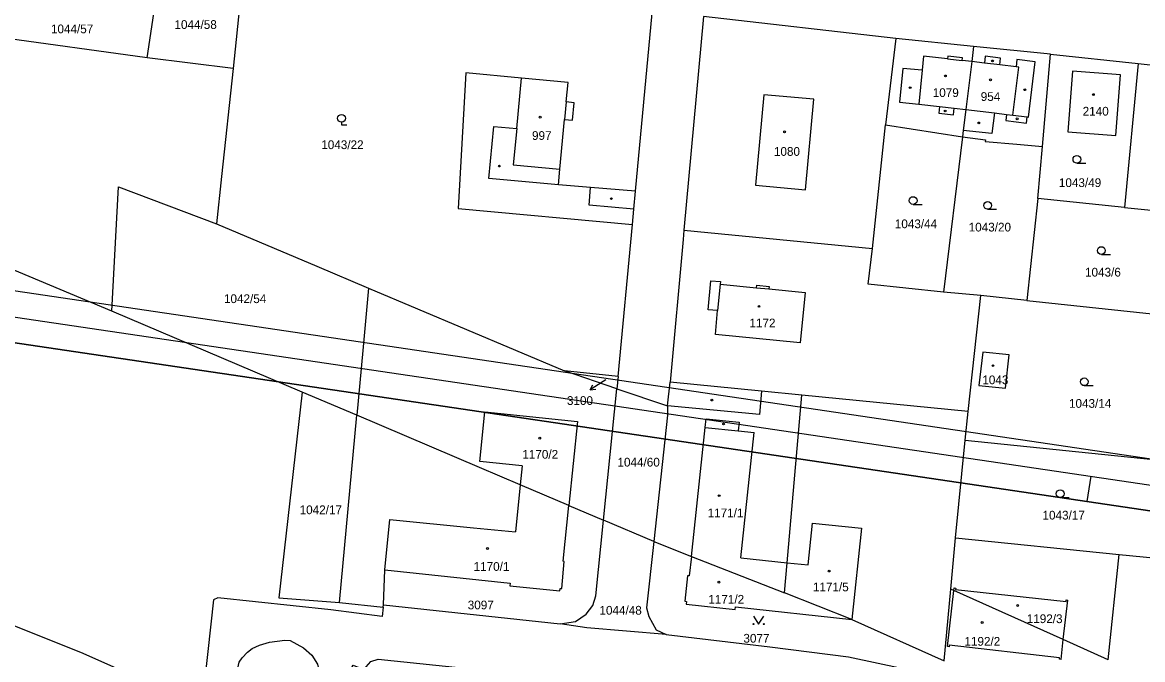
# Model space of a CAD drawing. Extents: x -779330 to -774454, y -1144748 to -1142831.
# Drawn here: x -775422.9 to -775205.5, y -1144345.1 to -1144221.4 of the extents above; entities that cross this region are included whole.
import ezdxf

# ---------------------------------------------------------------- set-up
doc = ezdxf.new("R2010")
doc.units = 0
for name, color, linetype in [('Hranice parcel', 7, 'Continuous'), ('Parcelní čísla', 7, 'Continuous'), ('Pop  PČ popisy', 7, 'Continuous'), ('Vnitřní kresba', 7, 'Continuous'), ('Vrstva 1', 7, 'Continuous'), ('Značky budov', 7, 'Continuous'), ('Značky kultur', 7, 'Continuous')]:
    doc.layers.add(name, color=color, linetype=linetype)

msp = doc.modelspace()

# ---------------------------------------------------------------- linework, layer by layer
at = {"layer": 'Hranice parcel'}
for p, q in [((-775380.44, -1144215.31), (-775382.05, -1144230.36)), ((-775398.7, -1144228.28), (-775397.42, -1144219.68)), ((-775303.9, -1144254.18), (-775300.69, -1144219.59)), ((-775290.72, -1144220.22), (-775294.52, -1144261.7)), ((-775253.4, -1144224.49), (-775290.72, -1144220.22)), ((-775398.7, -1144228.28), (-775442.24, -1144222.22)), ((-775253.4, -1144224.49), (-775255.39, -1144241.28)), ((-775238.28, -1144226.05), (-775253.4, -1144224.49)), ((-775223.36, -1144227.59), (-775238.28, -1144226.05)), ((-775382.05, -1144230.36), (-775398.7, -1144228.28)), ((-775224.92, -1144245.46), (-775223.36, -1144227.59)), ((-775223.36, -1144227.59), (-775206.34, -1144229.39)), ((-775206.34, -1144229.39), (-775208.99, -1144257.32)), ((-775206.34, -1144229.39), (-775195.14, -1144230.58)), ((-775257.93, -1144265.27), (-775255.39, -1144241.28)), ((-775255.39, -1144241.28), (-775240.44, -1144243.62)), ((-775240.44, -1144243.62), (-775244.14, -1144273.78)), ((-775225.81, -1144255.6), (-775224.92, -1144245.46)), ((-775405.59, -1144277.47), (-775404.31, -1144253.32)), ((-775404.31, -1144253.32), (-775385.27, -1144260.49)), ((-775225.81, -1144255.6), (-775227.98, -1144275.38)), ((-775208.99, -1144257.32), (-775225.81, -1144255.6)), ((-775208.99, -1144257.32), (-775197.16, -1144258.53)), ((-775307.31, -1144290.13), (-775304.52, -1144260.66)), ((-775294.52, -1144261.7), (-775257.93, -1144265.27)), ((-775355.73, -1144272.99), (-775317.7, -1144289.07)), ((-775236.87, -1144274.43), (-775244.14, -1144273.78)), ((-775239.33, -1144296.93), (-775236.87, -1144274.43)), ((-775227.98, -1144275.38), (-775236.87, -1144274.43)), ((-775227.98, -1144275.38), (-775199.27, -1144278.47)), ((-775368.6, -1144293.2), (-775405.59, -1144277.47)), ((-775307.31, -1144290.13), (-775317.7, -1144289.07)), ((-775307.55, -1144292.51), (-775317.7, -1144289.07)), ((-775307.31, -1144290.13), (-775307.55, -1144292.51)), ((-775297.71, -1144295.85), (-775297.22, -1144291.22)), ((-775279.43, -1144292.98), (-775297.22, -1144291.22)), ((-775358.04, -1144297.68), (-775368.6, -1144293.2)), ((-775310.14, -1144318.05), (-775307.55, -1144292.51)), ((-775307.55, -1144292.51), (-775297.71, -1144295.85)), ((-775271.6, -1144293.75), (-775279.43, -1144292.98)), ((-775239.33, -1144296.93), (-775271.6, -1144293.75)), ((-775361.4, -1144334), (-775358.04, -1144297.68)), ((-775239.94, -1144302.5), (-775239.33, -1144296.93)), ((-775241.77, -1144321.45), (-775239.94, -1144302.5)), ((-775239.94, -1144302.5), (-775200.81, -1144306.5)), ((-775317.99, -1144326.02), (-775316.86, -1144315.19)), ((-775316.86, -1144315.19), (-775310.14, -1144318.05)), ((-775300.37, -1144322.2), (-775310.14, -1144318.05)), ((-775300.37, -1144322.2), (-775293.07, -1144325.07)), ((-775242.71, -1144331.45), (-775241.77, -1144321.45)), ((-775241.77, -1144321.45), (-775210.05, -1144324.7)), ((-775212.14, -1144345.14), (-775210.05, -1144324.7)), ((-775210.05, -1144324.7), (-775202.71, -1144325.45)), ((-775293.07, -1144325.07), (-775293.48, -1144328.88)), ((-775293.07, -1144325.07), (-775275, -1144332.17)), ((-775244.01, -1144345.37), (-775242.71, -1144331.45)), ((-775261.93, -1144337.3), (-775275, -1144332.17)), ((-775361.4, -1144334), (-775352.89, -1144334.93)), ((-775352.89, -1144334.93), (-775352.84, -1144334.48)), ((-775352.84, -1144334.48), (-775318.54, -1144338.18)), ((-775284.53, -1144334.88), (-775261.93, -1144337.3)), ((-775261.93, -1144337.3), (-775244.01, -1144345.37))]:
    msp.add_line(p, q, dxfattribs=at)
for points in [[(-775238.28, -1144226.05), (-775238.64, -1144228.98), (-775239.78, -1144238.29), (-775240.29, -1144242.38), (-775240.44, -1144243.62)], [(-775382.05, -1144230.36), (-775384.29, -1144251.32), (-775385.27, -1144260.49)], [(-775303.9, -1144254.18), (-775312.63, -1144253.44), (-775318.9, -1144252.95), (-775318.61, -1144249.89), (-775317.7, -1144240.23), (-775316.15, -1144240.38), (-775315.82, -1144236.99), (-775317.37, -1144236.84), (-775317.02, -1144233.06), (-775326.05, -1144232.25), (-775336.89, -1144231.21), (-775338.37, -1144257.53), (-775304.52, -1144260.66)], [(-775219.08, -1144230.87), (-775219.98, -1144242.63), (-775210.66, -1144243.34), (-775209.76, -1144231.58), (-775219.08, -1144230.87)], [(-775405.59, -1144277.47), (-775483.88, -1144244.62), (-775508.4, -1144232.87)], [(-775240.44, -1144243.62), (-775235.97, -1144244.17), (-775236.02, -1144244.52), (-775229.92, -1144245.04), (-775224.92, -1144245.46)], [(-775607.93, -1144251.93), (-775592.73, -1144265.24), (-775577.44, -1144273.94), (-775563.67, -1144281.5), (-775543.76, -1144290.79), (-775411.19, -1144343.87), (-775388.13, -1144354.18)], [(-775304.52, -1144260.66), (-775304.24, -1144257.67), (-775303.9, -1144254.18)], [(-775385.27, -1144260.49), (-775365.81, -1144268.72), (-775355.73, -1144272.99)], [(-775294.52, -1144261.7), (-775294.69, -1144263.54), (-775297.22, -1144291.22)], [(-775244.14, -1144273.78), (-775258.75, -1144272.2), (-775257.93, -1144265.27)], [(-775355.73, -1144272.99), (-775356.87, -1144285.07), (-775358.04, -1144297.68)], [(-775231.36, -1144285.93), (-775236.51, -1144285.43), (-775237.28, -1144291.9), (-775232.07, -1144292.44), (-775231.36, -1144285.93)], [(-775368.6, -1144293.2), (-775373.15, -1144333.15), (-775361.4, -1144334)], [(-775275, -1144332.17), (-775274.48, -1144326.3), (-775271.6, -1144293.75)], [(-775297.71, -1144295.85), (-775297.7, -1144297.68), (-775300.37, -1144322.2)], [(-775316.86, -1144315.19), (-775326.32, -1144311.17), (-775334.23, -1144307.8), (-775358.04, -1144297.68)], [(-775318.54, -1144338.18), (-775315.57, -1144337.72), (-775313.52, -1144336.29), (-775312.2, -1144334.62), (-775311.63, -1144332.74), (-775310.14, -1144318.05)], [(-775300.37, -1144322.2), (-775301.77, -1144335.08), (-775301.32, -1144336.73), (-775299.9, -1144339.36), (-775297.97, -1144340.23)], [(-775352.84, -1144334.48), (-775352.58, -1144327.67), (-775328.26, -1144330.26), (-775328.31, -1144330.76), (-775318.6, -1144331.78), (-775318.54, -1144331.28), (-775318.25, -1144331.31), (-775317.74, -1144326.04), (-775317.99, -1144326.02)], [(-775293.48, -1144328.88), (-775293.83, -1144328.85), (-775294.35, -1144333.79), (-775294, -1144333.83), (-775294.06, -1144334.38), (-775284.59, -1144335.4), (-775284.53, -1144334.88)], [(-775212.14, -1144345.14), (-775220.88, -1144341.23), (-775242.11, -1144331.72), (-775242.71, -1144331.45)], [(-775352.89, -1144334.93), (-775353.07, -1144336.72), (-775363.07, -1144335.42), (-775385.03, -1144333.14), (-775385.87, -1144333.51), (-775388.13, -1144354.18)], [(-775297.97, -1144340.23), (-775313.36, -1144338.94), (-775318.54, -1144338.18)], [(-775382.3, -1144356.79), (-775381.59, -1144350.71), (-775381.29, -1144347.59), (-775380.83, -1144345.6), (-775380.26, -1144344.77), (-775379.26, -1144343.66), (-775378.34, -1144342.94), (-775376.9, -1144342.31), (-775374.94, -1144341.74), (-775371.99, -1144341.37), (-775370.97, -1144341.43), (-775368.36, -1144342.85), (-775366.76, -1144344.24), (-775365.64, -1144345.98), (-775364.98, -1144348.92), (-775365.24, -1144350.84), (-775365.71, -1144357.91), (-775366.41, -1144363.89)], [(-775297.97, -1144340.23), (-775277.83, -1144342.65), (-775262.59, -1144344.6), (-775251.95, -1144346.82), (-775244.32, -1144348.69)], [(-775362.68, -1144365.56), (-775362.08, -1144358.58), (-775360.56, -1144350.54), (-775360.06, -1144348.55), (-775358.72, -1144346.19), (-775356.63, -1144347.01), (-775355.33, -1144345.46), (-775353.88, -1144345), (-775329.64, -1144347.57), (-775327.49, -1144348.55), (-775323.08, -1144349.72), (-775321.94, -1144352.56), (-775321.52, -1144355.68), (-775321.75, -1144362.33), (-775323.77, -1144382.71)]]:
    msp.add_lwpolyline(points, dxfattribs=at)
at = {"layer": 'Pop  PČ popisy'}
for p, q in [((-775310.23, -1144291.1), (-775312.75, -1144292.73)), ((-775312.75, -1144292.73), (-775312.18, -1144291.77)), ((-775309.71, -1144290.77), (-775310.23, -1144291.1)), ((-775312.75, -1144292.73), (-775311.63, -1144292.61))]:
    msp.add_line(p, q, dxfattribs=at)
at = {"layer": 'Vnitřní kresba'}
for p, q in [((-775248.04, -1144227.94), (-775248.3, -1144230.68)), ((-775243.36, -1144228.46), (-775248.04, -1144227.94)), ((-775243.31, -1144227.96), (-775243.36, -1144228.46)), ((-775243.36, -1144228.46), (-775240.53, -1144228.77)), ((-775240.47, -1144228.27), (-775243.31, -1144227.96)), ((-775240.53, -1144228.77), (-775240.47, -1144228.27)), ((-775238.64, -1144228.98), (-775240.53, -1144228.77)), ((-775236.19, -1144229.29), (-775238.64, -1144228.98)), ((-775236.04, -1144227.97), (-775236.19, -1144229.29)), ((-775233.22, -1144229.64), (-775236.19, -1144229.29)), ((-775233.07, -1144228.31), (-775236.04, -1144227.97)), ((-775233.22, -1144229.64), (-775233.07, -1144228.31)), ((-775229.87, -1144228.62), (-775230.04, -1144230.03)), ((-775226.34, -1144229.05), (-775229.87, -1144228.62)), ((-775227.63, -1144239.78), (-775226.34, -1144229.05)), ((-775252.03, -1144230.33), (-775252.65, -1144236.88)), ((-775248.3, -1144230.68), (-775252.03, -1144230.33)), ((-775248.3, -1144230.68), (-775248.92, -1144237.29)), ((-775230.04, -1144230.03), (-775233.22, -1144229.64)), ((-775230.65, -1144239.41), (-775229.51, -1144230.1)), ((-775229.51, -1144230.1), (-775230.04, -1144230.03)), ((-775326.99, -1144242.01), (-775326.05, -1144232.25)), ((-775279.04, -1144235.44), (-775280.61, -1144252.99)), ((-775269.33, -1144236.28), (-775279.04, -1144235.44)), ((-775317.37, -1144236.84), (-775317.7, -1144240.23)), ((-775270.94, -1144253.9), (-775269.33, -1144236.28)), ((-775252.65, -1144236.88), (-775248.92, -1144237.29)), ((-775248.92, -1144237.29), (-775244.89, -1144237.73)), ((-775244.89, -1144237.73), (-775245.03, -1144239.02)), ((-775244.89, -1144237.73), (-775242.06, -1144238.04)), ((-775245.03, -1144239.02), (-775242.2, -1144239.33)), ((-775242.2, -1144239.33), (-775242.06, -1144238.04)), ((-775242.06, -1144238.04), (-775239.78, -1144238.29)), ((-775239.78, -1144238.29), (-775234.26, -1144238.97)), ((-775234.26, -1144238.97), (-775234.75, -1144242.97)), ((-775234.26, -1144238.97), (-775231.89, -1144239.26)), ((-775231.89, -1144239.26), (-775232.03, -1144240.45)), ((-775231.89, -1144239.26), (-775230.65, -1144239.41)), ((-775230.65, -1144239.41), (-775227.88, -1144239.75)), ((-775228.02, -1144240.94), (-775227.88, -1144239.75)), ((-775227.88, -1144239.75), (-775227.63, -1144239.78)), ((-775332.42, -1144251.67), (-775331.42, -1144241.59)), ((-775331.42, -1144241.59), (-775326.99, -1144242.01)), ((-775326.99, -1144242.01), (-775327.66, -1144249.03)), ((-775232.03, -1144240.45), (-775228.02, -1144240.94)), ((-775234.75, -1144242.97), (-775240.29, -1144242.38)), ((-775327.66, -1144249.03), (-775318.61, -1144249.89)), ((-775318.9, -1144252.95), (-775332.42, -1144251.67)), ((-775280.61, -1144252.99), (-775270.94, -1144253.9)), ((-775312.92, -1144256.88), (-775312.63, -1144253.44)), ((-775304.24, -1144257.67), (-775312.92, -1144256.88)), ((-775289.81, -1144277.19), (-775289.28, -1144271.56)), ((-775289.28, -1144271.56), (-775287.44, -1144271.73)), ((-775287.49, -1144272.23), (-775287.98, -1144277.36)), ((-775287.44, -1144271.73), (-775287.49, -1144272.23)), ((-775287.49, -1144272.23), (-775280.44, -1144272.91)), ((-775280.44, -1144272.91), (-775280.39, -1144272.41)), ((-775280.39, -1144272.41), (-775277.97, -1144272.65)), ((-775277.97, -1144272.65), (-775278.02, -1144273.15)), ((-775280.44, -1144272.91), (-775278.02, -1144273.15)), ((-775278.02, -1144273.15), (-775271, -1144273.83)), ((-775271, -1144273.83), (-775271.96, -1144283.61)), ((-775287.98, -1144277.36), (-775289.81, -1144277.19)), ((-775288.42, -1144282), (-775287.98, -1144277.36)), ((-775271.96, -1144283.61), (-775288.42, -1144282)), ((-775279.43, -1144292.98), (-775279.88, -1144297.55)), ((-775279.88, -1144297.55), (-775297.71, -1144295.85)), ((-775334.12, -1144306.68), (-775333.15, -1144296.98)), ((-775333.15, -1144296.98), (-775315.15, -1144298.9)), ((-775290.4, -1144300.03), (-775290.22, -1144298.34)), ((-775290.22, -1144298.34), (-775283.8, -1144299.03)), ((-775315.15, -1144298.9), (-775316.86, -1144315.19)), ((-775293.07, -1144325.07), (-775290.4, -1144300.03)), ((-775290.4, -1144300.03), (-775283.98, -1144300.72)), ((-775283.8, -1144299.03), (-775283.98, -1144300.72)), ((-775283.98, -1144300.72), (-775280.9, -1144301.05)), ((-775283.48, -1144325.34), (-775280.9, -1144301.05)), ((-775325.95, -1144307.49), (-775334.12, -1144306.68)), ((-775325.95, -1144307.49), (-775326.32, -1144311.17)), ((-775326.32, -1144311.17), (-775327.23, -1144320.33)), ((-775352.58, -1144327.67), (-775351.61, -1144317.92)), ((-775351.61, -1144317.92), (-775335.39, -1144319.52)), ((-775335.39, -1144319.52), (-775327.23, -1144320.33)), ((-775270.43, -1144326.73), (-775269.55, -1144318.6)), ((-775269.55, -1144318.6), (-775260.03, -1144319.62)), ((-775260.03, -1144319.62), (-775261.93, -1144337.3)), ((-775283.48, -1144325.34), (-775274.48, -1144326.3)), ((-775274.48, -1144326.3), (-775270.43, -1144326.73)), ((-775242.11, -1144331.72), (-775242.05, -1144331.19)), ((-775242.05, -1144331.19), (-775241.75, -1144331.22)), ((-775241.75, -1144331.22), (-775241.79, -1144331.52)), ((-775243.36, -1144342.6), (-775242.11, -1144331.72)), ((-775241.79, -1144331.52), (-775220.32, -1144333.83)), ((-775220.88, -1144341.23), (-775219.99, -1144333.56)), ((-775220.32, -1144333.83), (-775220.29, -1144333.53)), ((-775220.29, -1144333.53), (-775219.99, -1144333.56)), ((-775243.02, -1144342.34), (-775243.06, -1144342.64)), ((-775221.59, -1144344.75), (-775243.02, -1144342.34)), ((-775221.32, -1144345.09), (-775220.88, -1144341.23)), ((-775243.06, -1144342.64), (-775243.36, -1144342.6)), ((-775221.62, -1144345.05), (-775221.59, -1144344.75)), ((-775221.32, -1144345.09), (-775221.62, -1144345.05))]:
    msp.add_line(p, q, dxfattribs=at)
at = {"layer": 'Vrstva 1'}
msp.add_line((-775216.22, -1144314.43), (-775215.49, -1144309.48), dxfattribs=at)
for points in [[(-774799.29, -1144366.04), (-776045.7, -1144181.56), (-776089.18, -1144475.34), (-774842.77, -1144659.83)], [(-774846.98, -1144654.15), (-776083.5, -1144471.13), (-776041.48, -1144187.23), (-774804.97, -1144370.25)], [(-774810.64, -1144374.46), (-775834.48, -1144222.92), (-775875.04, -1144496.94), (-774851.19, -1144648.48)], [(-774851.19, -1144648.48), (-775875.04, -1144496.94), (-775834.48, -1144222.92), (-774810.64, -1144374.46)]]:
    msp.add_lwpolyline(points, close=True, dxfattribs=at)
at = {"layer": 'Značky budov'}
for centre in [(-775234.63, -1144228.87), (-775243.76, -1144231.79), (-775235.01, -1144232.55), (-775250.59, -1144234.06), (-775228.35, -1144234.46), (-775215.03, -1144235.41), (-775322.44, -1144239.8), (-775243.8, -1144238.59), (-775229.84, -1144240.12), (-775237.29, -1144240.91), (-775274.97, -1144242.64), (-775330.35, -1144249.29), (-775308.61, -1144255.61), (-775279.95, -1144276.53), (-775234.52, -1144288.04), (-775289.1, -1144294.72), (-775286.82, -1144299.37), (-775322.51, -1144302.13), (-775287.68, -1144313.28), (-775332.64, -1144323.54), (-775266.33, -1144327.92), (-775287.73, -1144330.09), (-775229.73, -1144334.61), (-775236.63, -1144337.92)]:
    msp.add_circle(centre, 0.175, dxfattribs=at)
at = {"layer": 'Značky kultur'}
for p, q in [((-775360.99, -1144240.76), (-775360.99, -1144241.26)), ((-775360.99, -1144241.26), (-775359.99, -1144241.26)), ((-775218.24, -1144248.73), (-775216.49, -1144248.73)), ((-775250.02, -1144256.73), (-775248.27, -1144256.73)), ((-775235.56, -1144257.68), (-775233.81, -1144257.68)), ((-775213.48, -1144266.44), (-775211.73, -1144266.44)), ((-775216.81, -1144291.92), (-775215.06, -1144291.92)), ((-775221.48, -1144313.65), (-775219.73, -1144313.65))]:
    msp.add_line(p, q, dxfattribs=at)
msp.add_lwpolyline([(-775281.02, -1144336.71), (-775280.02, -1144338.21), (-775279.02, -1144336.71)], dxfattribs=at)
for centre, radius in [((-775360.99, -1144240.01), 0.75), ((-775218.24, -1144247.98), 0.75), ((-775250.02, -1144255.98), 0.75), ((-775235.56, -1144256.93), 0.75), ((-775213.48, -1144265.69), 0.75), ((-775216.81, -1144291.17), 0.75), ((-775221.48, -1144312.9), 0.75), ((-775281.02, -1144338.21), 0.1), ((-775279.02, -1144338.21), 0.1)]:
    msp.add_circle(centre, radius, dxfattribs=at)

# ---------------------------------------------------------------- texts
at = {"layer": 'Parcelní čísla'}
for s, p in [('1044/57', (-775417.4, -1144223.5)), ('1044/58', (-775393.42, -1144222.66)), ('1079', (-775246.22, -1144235.88)), ('954', (-775236.9, -1144236.64)), ('2140', (-775217.11, -1144239.49)), ('1043/22', (-775364.92, -1144245.99)), ('997', (-775324.01, -1144244.21)), ('1080', (-775277.05, -1144247.3)), ('1043/49', (-775221.73, -1144253.36)), ('1043/44', (-775253.58, -1144261.35)), ('1043/20', (-775239.24, -1144261.99)), ('1043/6', (-775216.66, -1144270.74)), ('1042/54', (-775383.81, -1144275.89)), ('1172', (-775281.81, -1144280.61)), ('1043', (-775236.59, -1144291.65)), ('3100', (-775317.23, -1144295.67)), ('1043/14', (-775219.77, -1144296.22)), ('1170/2', (-775325.89, -1144306.11)), ('1044/60', (-775307.42, -1144307.63)), ('1042/17', (-775369.12, -1144316.88)), ('1171/1', (-775289.92, -1144317.48)), ('1043/17', (-775224.91, -1144317.92)), ('1170/1', (-775335.35, -1144327.89)), ('1171/5', (-775269.48, -1144331.86)), ('3097', (-775336.49, -1144335.36)), ('1171/2', (-775289.79, -1144334.26)), ('1044/48', (-775310.92, -1144336.39)), ('1192/3', (-775227.97, -1144338.03)), ('3077', (-775282.97, -1144341.83)), ('1192/2', (-775240.07, -1144342.42))]:
    msp.add_text(s, height=1.7, dxfattribs=at).set_placement(p)

doc.saveas('drawing.dxf')
